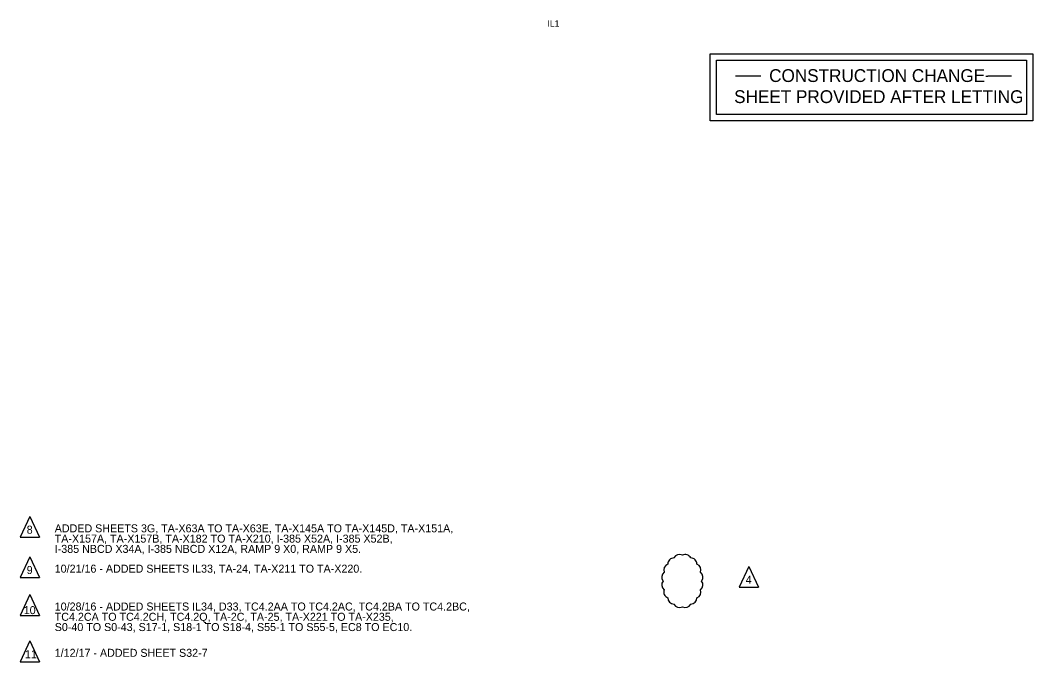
# Model space of a CAD drawing. Extents: x 116 to 2310, y 9 to 1131.
# Drawn here: x 1338 to 2128, y 622 to 1123 of the extents above; entities that cross this region are included whole.
import ezdxf

# ---------------------------------------------------------------- set-up
doc = ezdxf.new("R2010")
doc.units = 0
for name, color, linetype in [('BR_AUTO DIMENSION', 7, 'Continuous'), ('BR_TEXT', 7, 'Continuous'), ('RD_SHT_Bndy', 7, 'Continuous'), ('RD_SHT_TX', 7, 'Continuous'), ('RD_TX_Misc1', 7, 'Continuous')]:
    doc.layers.add(name, color=color, linetype=linetype)

# ---------------------------------------------------------------- blocks, each defined once
blk = doc.blocks.new('CHANGE')
at = {"layer": 'RD_TX_Misc1'}
for p, q in [((39.69, 34.94), (19.69, 34.94)), ((215.32, 34.94), (216.82, 34.94)), ((234.06, 34.94), (216.82, 34.94)), ((235.32, 34.94), (216.82, 34.94))]:
    blk.add_line(p, q, dxfattribs=at)
for points in [[(0, 52.41), (251.91, 52.41), (251.91, 0), (0, 0)], [(5, 47.41), (246.91, 47.41), (246.91, 5), (5, 5)]]:
    blk.add_lwpolyline(points, close=True, dxfattribs=at)
for s, p in [('CONSTRUCTION CHANGE', (46.07, 30.4)), ('SHEET PROVIDED AFTER LETTING', (18.72, 13.94))]:
    blk.add_text(s, height=10, dxfattribs=at).set_placement(p)

msp = doc.modelspace()

# ---------------------------------------------------------------- linework, layer by layer
at = {"layer": 'BR_AUTO DIMENSION'}
for p, q in [((1345.07, 735.48), (1337.57, 719.24)), ((1345.07, 735.48), (1352.57, 719.24)), ((1337.57, 719.24), (1352.57, 719.24)), ((1345.07, 703.97), (1337.57, 687.73)), ((1345.07, 703.97), (1352.57, 687.73)), ((1906.51, 696.39), (1899.01, 680.15)), ((1906.51, 696.39), (1914.01, 680.15)), ((1337.57, 687.73), (1352.57, 687.73)), ((1899.01, 680.15), (1914.01, 680.15)), ((1345.07, 674.41), (1337.57, 658.17)), ((1345.07, 674.41), (1352.57, 658.17)), ((1337.57, 658.17), (1352.57, 658.17)), ((1345.07, 638.23), (1337.57, 622)), ((1345.07, 638.23), (1352.57, 622)), ((1337.57, 622), (1352.57, 622))]:
    msp.add_line(p, q, dxfattribs=at)
for centre, start, end in [((1852.33, 700.85), 62.08305, 152.08305), ((1856.89, 700.85), 27.91951, 117.91951), ((1844.99, 693.66), 111.30965, 201.30965), ((1848.09, 698.26), 90.73228, 180.73228), ((1861.14, 698.26), 359.26491, 89.26491), ((1864.24, 693.66), 338.68765, 68.68765), ((1843.42, 688.02), 127.52301, 217.52301), ((1865.81, 688.02), 322.4768, 52.4768), ((1843.42, 682.09), 142.47699, 232.47699), ((1865.81, 682.09), 307.5232, 37.5232), ((1844.99, 676.46), 158.69035, 248.69035), ((1864.24, 676.46), 291.31235, 21.31235), ((1848.09, 671.86), 179.26772, 269.26772), ((1852.33, 669.27), 207.91695, 297.91695), ((1856.89, 669.27), 242.08049, 332.08049), ((1861.14, 671.86), 270.73509, 0.73509)]:
    msp.add_arc(centre, 4.87, start, end, dxfattribs=at)

# ---------------------------------------------------------------- block references
msp.add_blockref('CHANGE', (1876.32, 1044.47), dxfattribs=at)

# ---------------------------------------------------------------- texts
at = {"layer": 'BR_TEXT'}
for s, p in [('8', (1342.6, 722.04)), ('9', (1342.6, 690.53)), ('4', (1904.05, 682.95)), ('10', (1340.29, 659.19)), ('11', (1341.26, 624.79))]:
    msp.add_text(s, height=6.25, dxfattribs=at).set_placement(p)
at = {"layer": 'RD_SHT_Bndy'}
msp.add_text('IL1', height=5, dxfattribs=at).set_placement((1749.31, 1118.11))
at = {"layer": 'RD_SHT_TX'}
for s, p in [('ADDED SHEETS 3G, TA-X63A TO TA-X63E, TA-X145A TO TA-X145D, TA-X151A,', (1364.49, 723.09)), ('TA-X157A, TA-X157B, TA-X182 TO TA-X210, I-385 X52A, I-385 X52B, ', (1364.49, 715.06)), ('I-385 NBCD X34A, I-385 NBCD X12A, RAMP 9 X0, RAMP 9 X5.', (1364.49, 707.04)), ('10/21/16 - ADDED SHEETS IL33, TA-24, TA-X211 TO TA-X220.', (1364.49, 691.58)), ('10/28/16 - ADDED SHEETS IL34, D33, TC4.2AA TO TC4.2AC, TC4.2BA TO TC4.2BC, ', (1364.49, 662.02)), ('TC4.2CA TO TC4.2CH, TC4.2Q, TA-2C, TA-25, TA-X221 TO TA-X235, ', (1364.49, 654)), ('S0-40 TO S0-43, S17-1, S18-1 TO S18-4, S55-1 TO S55-5, EC8 TO EC10.', (1364.49, 645.97)), ('1/12/17 - ADDED SHEET S32-7', (1364.49, 625.85))]:
    msp.add_text(s, height=6.2499, dxfattribs=at).set_placement(p)

doc.saveas('drawing.dxf')
